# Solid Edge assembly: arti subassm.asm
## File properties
Author: Robert a Rhodes jr
Template: Normal.asm
Last saved by: CADCIM
Revision: 25
Application: Solid Edge
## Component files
rod bush lower.par
rod bush upper.par
articulated rod.par
piston.par
piston pin.par
piston pin plug.par
piston ring.par
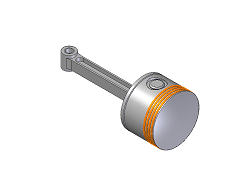
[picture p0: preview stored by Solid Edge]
